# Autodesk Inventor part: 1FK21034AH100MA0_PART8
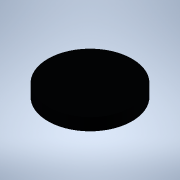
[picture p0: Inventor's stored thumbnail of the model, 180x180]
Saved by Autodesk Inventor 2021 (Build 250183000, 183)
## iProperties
Created: 2025-04
Part Number: 1FK21034AH100MA0_PART8
Material: Generic
Catalog Web Link: www.3dfindit.com
Description: -Servo synchronous motor
Document SubType Name: Modeling
Designer: psAdmin
Mass: 0.299142 g
Surface Area: 3.8585 cm^2
Volume: 0.299142 cm^3
Density: 1 g/cm^3
Appearance: PSOLRGB-38-46-56
Category: PARTsolutions
Title: 1FK21034AH100MA0_PART8
Author: Cadenas PARTsolutions
Comments: Servo synchronous motor
Sending System: PARTsolutions
Preprocessor: ST-DEVELOPER v19.3
PSOL_IDENT_0: {$CADENAS_DATA/23d-libs/siemens_ag/_cat_/39/97/1fk21034ah100ma0.prj},213 {VTYP=3D},{NB=1FK21034AH100
PSOL_IDENT_1: MA0_PART8},{LINA=1FK21034AH100MA0_PART8},{NN=1FK21034AH100MA0_PART8},{NOPRJ=TRUE},{DATE=19.08.2025 1
PSOL_IDENT_2: 4:00:33},{GEOMDATE=30.07.2025 02:02:21},{VERSION=},{LINEID=10},{WBVAR=},{WBNUMERIC=}  {NB=1FK21034AH
PSOL_IDENT_3: 100MA0_PART8},{LINA=1FK21034AH100MA0_PART8},{KT=DUMMY},{PREVIEW=../../../_pool_/d3/78/p_d211_xx_0093
PSOL_IDENT_4: 4j.png},{DESCSHORT=SIMOTICS S-1FK2 HD, SINAMICS S210 3AC 400V-480V, 1.01 Nm, 4500 rpm},{DESCLONG=SIM
PSOL_IDENT_5: OTICS S-1FK2 HD servo motor M0=1.27 Nm; PN = 0.48 kW at nN=4500 rpm (380-480 V); PN = 0.3 kW at nN=2
PSOL_IDENT_6: 500 rpm (200-240 V); with holding brake; degree of protection IP64; cylindrical shaft D14 x 30 mm; a
PSOL_IDENT_7: bsolute encoder 22-bit + 12-bit multiturn (encoder AM22DQC); with OCC interface; plug size M17, rota
PSOL_IDENT_8: table; SIMOTICS S-1FK2 servomotorfor a wide range of uses in industrial environments. SIMOTICS S‑1FK
PSOL_IDENT_9: 2 servomotors are compact synchronous motors with a high dynamic performance that set themselves apa
PSOL_IDENT_10: rt as a result of their high power density, degree of protection and overload capability. The motors
PSOL_IDENT_11: are available in two variants: as High Dynamic variant (highest dynamic performance as a result of
PSOL_IDENT_12: the low intrinsic moment of inertia for applications demanding a high dynamic performance with low m
PSOL_IDENT_13: oved masses) - and as Compact variant (precise and stable closed-loop control for medium up to large
PSOL_IDENT_14: moved masses as a result of a medium intrinsic moment of inertia). SIMOTICSS‑1FK2 servomotors fully
PSOL_IDENT_15: exploit their strengths in a system with the SINAMICSS210 frequency converter and simple connection
PSOL_IDENT_16: using the one cable connection (OCC). Advantages include the short control and positioning times, f
PSOL_IDENT_17: ast and precise correction of disturbing quantities as well as stable control with a high dynamic pe
PSOL_IDENT_18: rformance. The servo motors can be configured to address a wide range of requirements. For example w
PSOL_IDENT_19: ith and without holding brake, IP64 or IP65 degree of protection, singleturn or multiturn absolute e
PSOL_IDENT_20: ncoders - to name just a few. Further, the servomotors are available in different shaft heights exte
PSOL_IDENT_21: nding from 20 to 100. A shaft sealing ring is available to achieve an IP65 degree of protection and
PSOL_IDENT_22: for subsequent mounting at the motor or as spare part. SIMOTICS - the optimum motor for each and eve
PSOL_IDENT_23: ry motion control application.},{INTNO=195125454019},{SUPPLIERALTNO=1FK2103-4AH10-0MA0},{MANUID=1FK2
PSOL_IDENT_24: 1034AH100MA0},{MANUNAME=Siemens},{MANUTYPEDESC=SYNCHRONOUS MOTOR 1FK2 HD 1,27 NM},{AAU732=SIMOTICS},
PSOL_IDENT_25: {AAO057=S-1FK2},{AAU734=SIMOTICS S-1FK2 HD servo motor M0=1.27 Nm; PN = 0.48 kW at nN=4500 rpm (380-
PSOL_IDENT_26: 480 V); PN = 0.3 kW at nN=2500 rpm (200-240 V); with holding brake; degree of protection IP64; cylin
PSOL_IDENT_27: drical shaft D14 x 30 mm; absolute encoder 22-bit + 12-bit multiturn (encoder AM22DQC); with OCC int
PSOL_IDENT_28: erface; plug size M17, rotatable;},{AAW338=SYNCHRONOUS MOTOR 1FK2 HD 1,27 NM},{AAO742=SIMOTICS},{AAO
PSOL_IDENT_29: 663=4034106444921},{NOCUPEROU=1},{PRICEQUANTITY=1},{QUANTITYMIN=1},{QUANTITYINT=1},{CTN=85015100},{C
PSOL_IDENT_30: OO=RO},{AAO676=1FK2103-4AH10-0MA0},{AAO677=Siemens AG},{ORDERUNIT=C62},{CONTENTUNIT=C62}
NB: 1FK21034AH100MA0_PART8
NT: Servo synchronous motor
NBSYN: $MANUID._PART8
LINA: 1FK21034AH100MA0_PART8
CATALOG: SIEMENS
PREVIEW: ../../../_pool_/d3/78/p_d211_xx_00934j.png
DESCSHORT: SIMOTICS S-1FK2 HD, SINAMICS S210 3AC 400V-480V, 1.01 Nm, 4500 rpm
DESCLONG: SIMOTICS S-1FK2 HD servo motor M0=1.27 Nm; PN = 0.48 kW at nN=4500 rpm (380-480 V); PN = 0.3 kW at nN=2500 rpm (200-240 V); with holding brake; degree of protec
INTNO: 195125454019
SUPPLIERALTNO: 1FK2103-4AH10-0MA0
MANUID: 1FK21034AH100MA0
MANUNAME: Siemens
MANUTYPEDESC: SYNCHRONOUS MOTOR 1FK2 HD 1,27 NM
AAU732: SIMOTICS
AAO057: S-1FK2
AAU734: SIMOTICS S-1FK2 HD servo motor M0=1.27 Nm; PN = 0.48 kW at nN=4500 rpm (380-480 V); PN = 0.3 kW at nN=2500 rpm (200-240 V); with holding brake; degree of protec
AAW338: SYNCHRONOUS MOTOR 1FK2 HD 1,27 NM
AAO742: SIMOTICS
AAO663: 4034106444921.0
NOCUPEROU: 1
PRICEQUANTITY: 1
QUANTITYMIN: 1
QUANTITYINT: 1
CTN: 85015100
COO: RO
ARTICLENO: 1FK21034AH100MA0_PART8
BOMINFO: 1FK21034AH100MA0_PART8
CREATOR: CADENAS GmbH
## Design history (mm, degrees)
feature "2025_04_17_15_09_00_0330"
body "Solid1"
